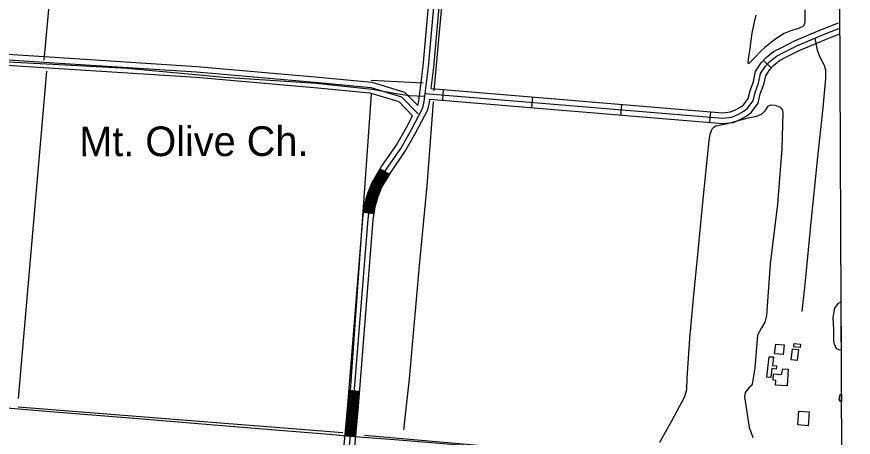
# Model space of a CAD drawing. Extents: x 3419139 to 3457078, y 540382 to 565875.
# Drawn here: x 3452584 to 3454925, y 552735 to 553912 of the extents above; entities that cross this region are included whole.
import ezdxf

# ---------------------------------------------------------------- set-up
doc = ezdxf.new("R2010")
doc.units = 0
for name, color, linetype in [('V-BLDG-OTLN', 7, 'Continuous'), ('V-DTCH-CNTR', 7, 'Continuous'), ('V-GRID-FRAM', 7, 'Continuous'), ('V-RAIL-TRAK', 7, 'Continuous'), ('V-ROAD-CNTR', 7, 'Continuous'), ('V-SITE-OTLN-IDEN', 7, 'Continuous'), ('V-SITE-VEGE', 7, 'Continuous'), ('V-TOPO-SHOR', 7, 'Continuous')]:
    doc.layers.add(name, color=color, linetype=linetype)

msp = doc.modelspace()

# ---------------------------------------------------------------- linework, layer by layer
at = {"layer": 'V-BLDG-OTLN'}
for points in [[(3454731.6, 552993.6), (3454728.7, 552966.3), (3454705, 552968.8), (3454708.2, 552995.2)], [(3454776.6, 552986), (3454759, 552988), (3454760.1, 552997.5), (3454777.3, 552995.5)], [(3454771.8, 552980.4), (3454768.3, 552949.9), (3454751.4, 552951.9), (3454755.1, 552982.6)], [(3454689.4, 552960.4), (3454702.1, 552959.6), (3454699.6, 552936.1), (3454710.2, 552935), (3454709.2, 552925.7), (3454697.4, 552926.9), (3454694.8, 552902.2), (3454683.5, 552903.4)], [(3454743, 552925.1), (3454740.3, 552879), (3454707.9, 552880.9), (3454708.6, 552893.7), (3454700.8, 552894.2), (3454701.8, 552912.1), (3454724.5, 552910.7), (3454728.5, 552926.6)], [(3454801.4, 552805.6), (3454798.8, 552767.3), (3454769.8, 552769.2), (3454772.5, 552808.2)]]:
    msp.add_lwpolyline(points, close=True, dxfattribs=at)
at = {"layer": 'V-DTCH-CNTR'}
for points in [[(3451138.4, 553905.2), (3451317.8, 553889.8), (3451523.1, 553872.9), (3451688.3, 553858.3), (3451852.5, 553844.7), (3452021.1, 553826.2), (3452229.3, 553807.3), (3452541.5, 553786.3), (3452667.6, 553780.2), (3452893.1, 553767.5), (3453165, 553743), (3453421.6, 553726.2), (3453578.6, 553709.2), (3453645.5, 553697.3), (3453682.3, 553691.1), (3453726.5, 553689.1)], [(3454817.6, 553851.3), (3454824.2, 553818.2), (3454831.6, 553799), (3454843.8, 553775.8), (3454847.5, 553763.4), (3454847.7, 553739.1), (3454839.8, 553656.8), (3454824.6, 553510.1), (3454806.7, 553337), (3454790.1, 553162.3), (3454781.3, 553087.1)]]:
    msp.add_lwpolyline(points, dxfattribs=at)
at = {"layer": 'V-GRID-FRAM'}
msp.add_lwpolyline([(3423200.9, 563955.1), (3454837.9, 564093.1), (3454925.2, 545910.2), (3423272.3, 545772.1), (3423200.9, 563955.1)], dxfattribs=at)
at = {"layer": 'V-RAIL-TRAK'}
msp.add_lwpolyline([(3454811.8, 552655.3), (3454749.2, 552653.2), (3454636.5, 552653.2), (3454545.2, 552655.8), (3454448.5, 552661.3), (3454271.3, 552675.4), (3454052.8, 552693.8), (3453867.5, 552709.3), (3453653.8, 552726.6), (3453517.4, 552737.4), (3453459.7, 552742.3), (3453318.8, 552753.5), (3453114.5, 552770.6), (3452923.7, 552786.2), (3452689.8, 552805.5), (3452476.7, 552822.8)], dxfattribs=at)
at = {"layer": 'V-ROAD-CNTR'}
for p, q in [((3454673.7, 553789.3), (3454695.3, 553768.5)), ((3453777.9, 553707.9), (3453775.5, 553678)), ((3454027.1, 553687.3), (3454024.6, 553657.4)), ((3454276.2, 553666.6), (3454273.7, 553636.7)), ((3454525.4, 553646), (3454522.9, 553616.1)), ((3453601.4, 553486.1), (3453627.3, 553471.1)), ((3453554.7, 553365.2), (3453584.4, 553361.3)), ((3453513.6, 552866.2), (3453543.5, 552863.8)), ((3453502.8, 552741.8), (3453532.7, 552739.1))]:
    msp.add_line(p, q, dxfattribs=at)
for points in [[(3453743.6, 553710.8), (3453750.9, 553770.3), (3453808.5, 554409.6), (3453866.1, 555090.2), (3453924.5, 555746.1), (3453960.7, 556128.7), (3453989.9, 556466.5), (3454026.7, 556906.9), (3454095.8, 557647.2), (3454174.1, 558513.6), (3454238.3, 559210.9), (3454299.7, 559949.6), (3454368.1, 560749.2)], [(3453343.2, 550823.7), (3453344.4, 550930), (3453379, 551270.2), (3453449.5, 551985.5), (3453525.2, 552823.2), (3453567.1, 553344.9), (3453572.2, 553383.2), (3453581, 553413.4), (3453591.7, 553439.5), (3453616, 553481.4), (3453658.6, 553543.1), (3453688, 553594.5), (3453720.1, 553656.5), (3453724.1, 553674.2), (3453736, 553771.9), (3453793.6, 554410.9), (3453851.2, 555091.5), (3453909.6, 555747.5), (3453945.8, 556130), (3453974.9, 556467.7), (3454011.8, 556908.2), (3454080.8, 557648.6)], [(3453706.2, 553662.9), (3453709.3, 553676.7), (3453721.1, 553773.5), (3453778.6, 554412.2), (3453836.2, 555092.8), (3453894.6, 555748.9), (3453930.8, 556131.4), (3453960, 556469), (3453974.2, 556638.4)], [(3451121.7, 553911.7), (3451277, 553910.9), (3451695, 553885.8), (3451897.6, 553850), (3452338.8, 553820.6), (3452661.1, 553800), (3453088.4, 553772.4), (3453429.7, 553742.7), (3453578.1, 553728.8), (3453669.2, 553700.5), (3453706.2, 553662.9)], [(3451103.7, 553896.8), (3451276.5, 553895.9), (3451693.2, 553870.9), (3451895.8, 553835.1), (3452337.8, 553805.6), (3452660.1, 553785), (3453087.3, 553757.5), (3453428.3, 553727.8), (3453575.1, 553714), (3453661.2, 553687.3), (3453707.9, 553639.7)], [(3453743.6, 553710.8), (3454560.1, 553643.1), (3454581.8, 553645.5), (3454597.3, 553652.4), (3454610.8, 553659.7), (3454618.8, 553666), (3454631.2, 553682.7), (3454636.2, 553704.4), (3454645.8, 553730.3), (3454651.9, 553758.3), (3454667.6, 553783), (3454681.8, 553797.7), (3454701.7, 553814.2), (3454725.3, 553826.1), (3454761.1, 553844.1), (3454836.2, 553875.8), (3454884.3, 553894.7)], [(3451117.8, 553881.8), (3451276, 553880.9), (3451691.5, 553856), (3451894, 553820.1), (3452336.8, 553790.6), (3452659.1, 553770), (3453086.2, 553742.5), (3453427, 553712.9), (3453572.2, 553699.2), (3453653.1, 553674.1), (3453691.9, 553634.6)], [(3453726.9, 553697.1), (3454560.4, 553628), (3454585.8, 553630.9), (3454603.9, 553638.9), (3454619.1, 553647.1), (3454629.6, 553655.5), (3454645.2, 553676.3), (3454650.6, 553700.1), (3454660.2, 553726), (3454666, 553752.5), (3454679.4, 553773.7), (3454692, 553786.6), (3454710, 553801.5), (3454732.1, 553812.7), (3454767.4, 553830.5), (3454841.9, 553861.9), (3454884.4, 553878.7)], [(3453740, 553681), (3454560.6, 553612.9), (3454589.8, 553616.2), (3454610.5, 553625.4), (3454627.4, 553634.6), (3454640.5, 553644.9), (3454659.1, 553669.9), (3454665, 553695.8), (3454674.7, 553721.8), (3454680.1, 553746.7), (3454691.3, 553764.3), (3454702.2, 553775.6), (3454718.3, 553788.9), (3454738.8, 553799.3), (3454773.7, 553816.9), (3454847.5, 553848), (3454884.4, 553862.6)], [(3453444.4, 551781), (3453464.5, 551984.1), (3453540.1, 552821.9), (3453582, 553343.3), (3453586.9, 553380), (3453595.2, 553408.4), (3453605.2, 553432.9), (3453628.7, 553473.4), (3453671.3, 553535.1), (3453701.2, 553587.3), (3453734.3, 553651.3), (3453738.9, 553671.6), (3453740, 553681)], [(3453414.6, 551783.9), (3453434.6, 551987), (3453510.3, 552824.4), (3453552.2, 553346.5), (3453557.5, 553386.3), (3453566.9, 553418.3), (3453578.2, 553446.2), (3453603.3, 553489.5), (3453645.9, 553551.1), (3453674.9, 553601.7), (3453691.9, 553634.6)], [(3453557.6, 553364.8), (3453560.4, 553385.6), (3453569.7, 553417.3), (3453580.9, 553444.8), (3453604, 553484.6)], [(3453560.6, 553364.4), (3453563.3, 553385), (3453572.5, 553416.4), (3453583.6, 553443.5), (3453606.6, 553483.1)], [(3453563.6, 553364), (3453566.3, 553384.4), (3453575.4, 553415.4), (3453586.3, 553442.2), (3453609.2, 553481.6)], [(3453566.6, 553363.6), (3453569.2, 553383.8), (3453578.2, 553414.4), (3453589, 553440.9), (3453611.8, 553480.1)], [(3453569.5, 553363.3), (3453572.2, 553383.2), (3453581, 553413.4), (3453591.7, 553439.5), (3453614.4, 553478.6)], [(3453572.5, 553362.9), (3453575.1, 553382.5), (3453583.9, 553412.4), (3453594.4, 553438.2), (3453616.9, 553477.1)], [(3453575.5, 553362.5), (3453578.1, 553381.9), (3453586.7, 553411.4), (3453597.1, 553436.9), (3453619.5, 553475.6)], [(3453578.5, 553362.1), (3453581, 553381.3), (3453589.5, 553410.4), (3453599.8, 553435.6), (3453622.1, 553474.1)], [(3453581.4, 553361.7), (3453584, 553380.7), (3453592.4, 553409.4), (3453602.5, 553434.2), (3453624.7, 553472.6)], [(3453505.8, 552741.5), (3453513.2, 552824.2), (3453516.6, 552865.9)], [(3453508.8, 552741.2), (3453516.2, 552823.9), (3453519.6, 552865.7)], [(3453511.7, 552741), (3453519.2, 552823.7), (3453522.6, 552865.4)], [(3453514.7, 552740.7), (3453522.2, 552823.4), (3453525.6, 552865.2)], [(3453517.7, 552740.4), (3453525.2, 552823.2), (3453528.6, 552865)], [(3453520.7, 552740.2), (3453528.2, 552822.9), (3453531.5, 552864.7)], [(3453523.7, 552739.9), (3453531.2, 552822.7), (3453534.5, 552864.5)], [(3453526.7, 552739.6), (3453534.2, 552822.4), (3453537.5, 552864.2)], [(3453529.7, 552739.4), (3453537.2, 552822.2), (3453540.5, 552864)]]:
    msp.add_lwpolyline(points, dxfattribs=at)
at = {"layer": 'V-SITE-VEGE'}
for p, q in [((3454789.3, 553931.4), (3454789.7, 553910.9)), ((3454648.8, 553896.5), (3454653, 553915.9)), ((3454789.7, 553910.9), (3454789.5, 553898.5)), ((3454642.6, 553866.1), (3454648.8, 553896.5)), ((3454783.9, 553884.1), (3454772.1, 553878.9)), ((3454785.4, 553885.4), (3454783.9, 553884.1)), ((3454788.6, 553891.8), (3454785.4, 553885.4)), ((3454789.5, 553898.5), (3454788.6, 553891.8)), ((3454639.5, 553845.3), (3454642.6, 553866.1)), ((3454722.2, 553859.2), (3454707.6, 553849.1)), ((3454731.9, 553864.7), (3454722.2, 553859.2)), ((3454745.4, 553870.5), (3454731.9, 553864.7)), ((3454750.4, 553872.5), (3454745.4, 553870.5)), ((3454768.2, 553877.6), (3454750.4, 553872.5)), ((3454772.1, 553878.9), (3454768.2, 553877.6)), ((3454635.8, 553816.3), (3454639.5, 553845.3)), ((3454696.4, 553840.1), (3454677.8, 553825.5)), ((3454707.6, 553849.1), (3454696.4, 553840.1)), ((3454633.1, 553800), (3454635.8, 553816.3)), ((3454665.9, 553814), (3454650.1, 553798)), ((3454677.8, 553825.5), (3454665.9, 553814)), ((3454631.4, 553783.7), (3454633.1, 553800)), ((3454641.4, 553788.9), (3454632.4, 553780.2)), ((3454650.1, 553798), (3454641.4, 553788.9)), ((3454632.4, 553780.2), (3454631.4, 553783.7)), ((3454873.5, 553096.1), (3454883.5, 553110.2)), ((3454883.5, 553110.2), (3454890.6, 553113.9)), ((3454890.6, 553113.9), (3454891.3, 552979.5)), ((3454868.5, 553069.6), (3454873.5, 553096.1)), ((3454870.1, 553052.1), (3454868.5, 553069.6)), ((3454871.2, 553037.2), (3454870.1, 553052.1)), ((3454870.8, 553017.7), (3454871.2, 553037.2)), ((3454871.2, 553004.1), (3454870.8, 553017.7)), ((3454873, 552995), (3454871.2, 553004.1)), ((3454878.6, 552982.6), (3454873, 552995)), ((3454888.3, 552978.6), (3454878.6, 552982.6)), ((3454891.3, 552979.5), (3454888.3, 552978.6)), ((3454885.9, 552840.6), (3454888.7, 552854.2)), ((3454888.7, 552854.2), (3454891.9, 552855.2)), ((3454891.9, 552855.2), (3454892, 552834.3)), ((3454889.7, 552835.4), (3454885.9, 552840.6)), ((3454892, 552834.3), (3454889.7, 552835.4))]:
    msp.add_line(p, q, dxfattribs=at)
msp.add_lwpolyline([(3454383.4, 552721.6), (3454417.8, 552780.8), (3454453.6, 552848.5), (3454459.5, 552869.4), (3454460, 552900.2), (3454467.5, 553011.4), (3454476.7, 553113.8), (3454490.8, 553255.6), (3454503.9, 553391.6), (3454522.1, 553565.4), (3454524.7, 553582.8), (3454528.1, 553593.7), (3454532.5, 553601.1), (3454540.3, 553606.8), (3454573.5, 553613.3), (3454631, 553629.1), (3454654.1, 553633.9), (3454668.1, 553638.8), (3454678.3, 553648.7), (3454687.2, 553661.2), (3454695.7, 553665.5), (3454707, 553664.7), (3454720.2, 553658.3), (3454727.2, 553650.1), (3454727.7, 553643), (3454725, 553543.4), (3454713.2, 553387), (3454692.5, 553220.3), (3454682.2, 553075.5), (3454677.3, 553057.2), (3454668, 553041.2), (3454656.9, 553020.3), (3454649.8, 552929.2), (3454642.2, 552883.7), (3454639.6, 552879.2), (3454633.7, 552874.2), (3454622.4, 552860.4), (3454620.6, 552847.8), (3454633.7, 552762.8), (3454644.2, 552734.2)], dxfattribs=at)
at = {"layer": 'V-TOPO-SHOR'}
for p, q in [((3452667.7, 553759.8), (3452587.7, 552843.3)), ((3453721.3, 553726.2), (3453576.2, 553733.2)), ((3453576.4, 553695), (3453511.7, 552786.3)), ((3452587.8, 552820.4), (3453496.6, 552748.1))]:
    msp.add_line(p, q, dxfattribs=at)
for points in [[(3452898.5, 556705.4), (3452798.1, 555363.5), (3452710.9, 554347.8), (3452659.9, 553790.3)], [(3453836.7, 554649.1), (3453835.8, 554639.3), (3453819.5, 554447.5), (3453789.5, 554123.4), (3453763.1, 553838.2), (3453751.7, 553704.3)], [(3453749.8, 553673.9), (3453731.4, 553438.5), (3453710.3, 553215.9), (3453682, 552898.2), (3453666.9, 552756)], [(3453557.7, 552740.7), (3454214.5, 552682.5), (3454435.9, 552675.8), (3454657.3, 552669.2), (3454779.4, 552677.3)]]:
    msp.add_lwpolyline(points, dxfattribs=at)

# ---------------------------------------------------------------- texts
at = {"layer": 'V-SITE-OTLN-IDEN'}
msp.add_text('Mt. Olive Ch.', height=83, rotation=0.088, dxfattribs=at).set_placement((3452759.1, 553521.3))

doc.saveas('drawing.dxf')
